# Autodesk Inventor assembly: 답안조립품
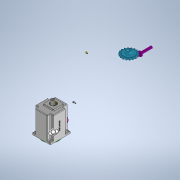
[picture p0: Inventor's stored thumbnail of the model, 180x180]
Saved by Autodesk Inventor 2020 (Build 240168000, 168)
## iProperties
Created: 2022-01
Part Number: 답안조립품
Document SubType Name: Assembly
Designer: user
Author: user
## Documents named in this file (16)
- C:\Users\user\Desktop\720112V1010\답안조립품.iam
- C:\Users\user\Desktop\720112V1010\멈춤나사 M3.ipt
- C:\Users\user\Desktop\720112V1010\메인 축.ipt
- C:\Users\user\Desktop\720112V1010\베어링 608.ipt
- C:\Users\user\Desktop\720112V1010\베어링 6003.ipt
- C:\Users\user\Desktop\720112V1010\본체.ipt
- C:\Users\user\Desktop\720112V1010\볼트 M4 x 10.ipt
- C:\Users\user\Desktop\720112V1010\부시.ipt
- C:\Users\user\Desktop\720112V1010\상부 캡.ipt
- C:\Users\user\Desktop\720112V1010\서브 축.ipt
- C:\Users\user\Desktop\720112V1010\스프로킷.ipt
- C:\Users\user\Desktop\720112V1010\슬라이더.ipt
- C:\Users\user\Desktop\720112V1010\오일 실 8 x 22 x 7.ipt
- C:\Users\user\Desktop\720112V1010\오일 실 17 x 32 x 8.ipt
- C:\Users\user\Desktop\720112V1010\커버.ipt
- C:\Users\user\Desktop\720112V1010\키 5 x 5.ipt
